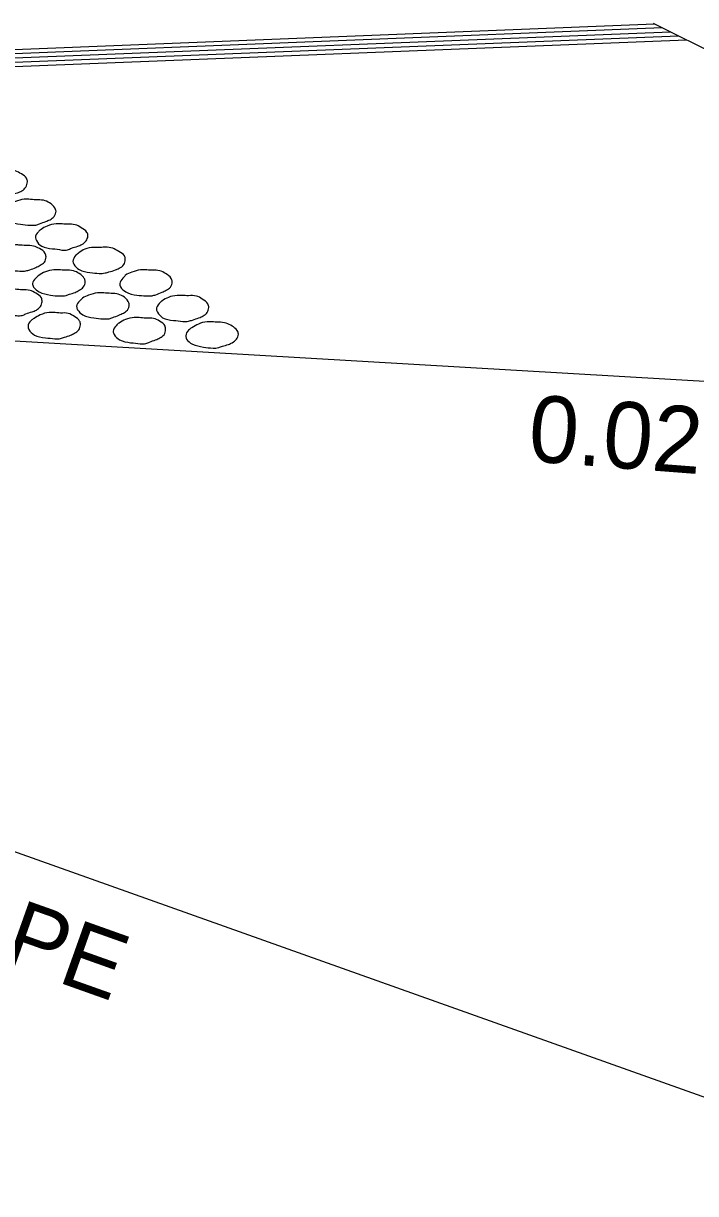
# Model space of a CAD drawing. Extents: x -2842 to 2681, y -2139 to 474.
# Drawn here: x 2035 to 2095.5, y -40.3 to 65.1 of the extents above; entities that cross this region are included whole.
import ezdxf

# ---------------------------------------------------------------- set-up
doc = ezdxf.new("R2010")
doc.units = 0
doc.layers.add('R_Grid', color=7, linetype='Continuous')

msp = doc.modelspace()

# ---------------------------------------------------------------- linework, layer by layer
at = {"layer": 'R_Grid'}
for p, q in [((1449.13, 38.68), (2093.27, 64.39)), ((1449.98, 39.13), (2092.52, 64.76)), ((1450.73, 39.48), (2091.83, 65.1)), ((2215.91, 3.06), (2091.72, 65.14)), ((1447.46, 37.85), (2094.71, 63.67)), ((1448.3, 38.28), (2093.98, 64.03)), ((2010.36, 37.94), (2164.16, 28.93)), ((1946.93, 21.56), (2120.76, -40.3))]:
    msp.add_line(p, q, dxfattribs=at)
for points in [[(2033.03, 49.58), (2032.18, 49.68), (2031.25, 49.94), (2030.71, 50.42), (2030.64, 50.66), (2030.92, 51.23), (2031.21, 51.44), (2031.74, 51.77), (2032.52, 51.93), (2032.92, 51.93), (2033.55, 51.95), (2034.25, 51.86), (2034.82, 51.57), (2035.28, 51.19), (2035.36, 50.85), (2035.21, 50.39), (2034.86, 50.05), (2034.45, 49.88), (2033.89, 49.74), (2033.55, 49.64), (2033.03, 49.58)], [(2035.6, 46.95), (2034.72, 47.04), (2033.76, 47.3), (2033.29, 47.77), (2033.2, 48.06), (2033.46, 48.56), (2033.69, 48.81), (2034.28, 49.1), (2035.06, 49.29), (2035.49, 49.29), (2036.11, 49.24), (2036.81, 49.2), (2037.35, 48.97), (2037.83, 48.52), (2037.93, 48.21), (2037.77, 47.75), (2037.39, 47.45), (2037.01, 47.29), (2036.45, 47.08), (2036.11, 46.97), (2035.6, 46.95)], [(2038.45, 44.72), (2037.6, 44.84), (2036.64, 45.07), (2036.16, 45.58), (2036.08, 45.83), (2036.34, 46.35), (2036.58, 46.57), (2037.14, 46.87), (2037.94, 47.08), (2038.33, 47.08), (2038.96, 47.04), (2039.65, 47), (2040.2, 46.73), (2040.72, 46.31), (2040.8, 45.97), (2040.64, 45.55), (2040.27, 45.22), (2039.89, 45.06), (2039.32, 44.88), (2038.96, 44.74), (2038.45, 44.72)], [(2034.68, 42.82), (2033.84, 42.9), (2032.88, 43.17), (2032.39, 43.65), (2032.31, 43.92), (2032.59, 44.43), (2032.82, 44.67), (2033.39, 44.98), (2034.18, 45.17), (2034.58, 45.17), (2035.21, 45.13), (2035.91, 45.08), (2036.43, 44.86), (2036.96, 44.41), (2037.03, 44.1), (2036.88, 43.62), (2036.5, 43.35), (2036.12, 43.15), (2035.57, 42.94), (2035.21, 42.84), (2034.68, 42.82)], [(2041.83, 42.6), (2040.99, 42.69), (2040.02, 42.95), (2039.54, 43.44), (2039.46, 43.69), (2039.7, 44.21), (2039.99, 44.46), (2040.52, 44.79), (2041.32, 44.95), (2041.72, 44.95), (2042.35, 44.97), (2043.04, 44.88), (2043.59, 44.58), (2044.09, 44.19), (2044.16, 43.87), (2044.03, 43.4), (2043.62, 43.07), (2043.28, 42.92), (2042.7, 42.74), (2042.35, 42.65), (2041.83, 42.6)], [(2038.28, 40.58), (2037.42, 40.65), (2036.42, 40.95), (2035.91, 41.38), (2035.82, 41.7), (2036.1, 42.17), (2036.38, 42.42), (2036.97, 42.76), (2037.74, 42.93), (2038.17, 42.93), (2038.8, 42.9), (2039.51, 42.84), (2040.02, 42.6), (2040.48, 42.15), (2040.56, 41.86), (2040.39, 41.37), (2040.03, 41.1), (2039.65, 40.9), (2039.14, 40.73), (2038.83, 40.62), (2038.28, 40.58)], [(2046.06, 40.59), (2045.21, 40.65), (2044.23, 40.94), (2043.74, 41.4), (2043.67, 41.7), (2043.96, 42.18), (2044.17, 42.43), (2044.76, 42.73), (2045.54, 42.93), (2045.94, 42.93), (2046.58, 42.89), (2047.28, 42.85), (2047.8, 42.6), (2048.31, 42.16), (2048.4, 41.86), (2048.24, 41.37), (2047.86, 41.1), (2047.48, 40.92), (2046.91, 40.69), (2046.58, 40.6), (2046.06, 40.59)], [(2034.36, 38.81), (2033.51, 38.91), (2032.54, 39.17), (2032.02, 39.65), (2031.97, 39.92), (2032.21, 40.45), (2032.52, 40.64), (2033.05, 40.97), (2033.84, 41.19), (2034.26, 41.19), (2034.89, 41.12), (2035.6, 41.08), (2036.11, 40.82), (2036.61, 40.4), (2036.67, 40.06), (2036.53, 39.63), (2036.16, 39.31), (2035.77, 39.15), (2035.21, 38.96), (2034.89, 38.83), (2034.36, 38.81)], [(2042.17, 38.51), (2041.33, 38.6), (2040.36, 38.87), (2039.88, 39.34), (2039.79, 39.63), (2040.07, 40.14), (2040.31, 40.38), (2040.87, 40.65), (2041.66, 40.86), (2042.08, 40.86), (2042.72, 40.82), (2043.4, 40.77), (2043.95, 40.56), (2044.44, 40.09), (2044.52, 39.81), (2044.36, 39.31), (2044, 39.04), (2043.6, 38.86), (2043.04, 38.63), (2042.72, 38.53), (2042.17, 38.51)], [(2049.35, 38.29), (2048.5, 38.38), (2047.53, 38.62), (2047.07, 39.12), (2046.98, 39.37), (2047.23, 39.89), (2047.47, 40.12), (2048.05, 40.45), (2048.83, 40.62), (2049.24, 40.62), (2049.87, 40.6), (2050.58, 40.57), (2051.1, 40.3), (2051.61, 39.86), (2051.68, 39.53), (2051.55, 39.1), (2051.18, 38.78), (2050.8, 38.61), (2050.21, 38.41), (2049.87, 38.31), (2049.35, 38.29)], [(2037.83, 36.72), (2036.97, 36.81), (2035.98, 37.06), (2035.49, 37.56), (2035.41, 37.83), (2035.68, 38.36), (2035.95, 38.55), (2036.51, 38.87), (2037.31, 39.09), (2037.71, 39.09), (2038.33, 39.04), (2039.03, 39.01), (2039.59, 38.72), (2040.06, 38.32), (2040.13, 37.97), (2039.98, 37.53), (2039.61, 37.22), (2039.24, 37.05), (2038.7, 36.86), (2038.33, 36.74), (2037.83, 36.72)], [(2045.51, 36.28), (2044.65, 36.37), (2043.65, 36.64), (2043.17, 37.11), (2043.08, 37.4), (2043.34, 37.9), (2043.61, 38.14), (2044.18, 38.45), (2044.98, 38.63), (2045.42, 38.63), (2046.03, 38.58), (2046.72, 38.55), (2047.25, 38.32), (2047.75, 37.86), (2047.8, 37.56), (2047.66, 37.09), (2047.28, 36.8), (2046.9, 36.63), (2046.36, 36.42), (2046.03, 36.29), (2045.51, 36.28)], [(2052.07, 35.87), (2051.21, 35.97), (2050.21, 36.25), (2049.69, 36.7), (2049.62, 36.98), (2049.87, 37.5), (2050.16, 37.72), (2050.75, 38.05), (2051.53, 38.24), (2051.95, 38.24), (2052.55, 38.22), (2053.26, 38.13), (2053.79, 37.87), (2054.25, 37.46), (2054.35, 37.13), (2054.19, 36.68), (2053.8, 36.37), (2053.46, 36.21), (2052.92, 36.04), (2052.58, 35.93), (2052.07, 35.87)]]:
    msp.add_spline(points, degree=3, dxfattribs=at)

# ---------------------------------------------------------------- texts
for s, rotation, p in [("0.020'/'", 355.6232, (2080.34, 25.71)), ('EXISTING SLOPE', 340.4108, (1980.38, -0.71))]:
    msp.add_text(s, height=6, rotation=rotation, dxfattribs=at).set_placement(p)

doc.saveas('drawing.dxf')
